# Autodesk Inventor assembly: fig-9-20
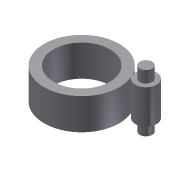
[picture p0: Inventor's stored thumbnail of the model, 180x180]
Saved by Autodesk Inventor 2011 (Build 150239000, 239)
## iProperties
Shininess: 64.0
Length Units: 11269
Angle Units: 11279
Time Units: 11290
Mass Units: 11283
Length Display Precision: 3
Angle Display Precision: 2
Created: 2002-01
Part Number: fig-9-20
Document SubType Name: Assembly
Designer: ***
Density: 0.0
Volumn: 0.0
Area: 0.0
PropertySet Name: Model Information
Control State: 0
Master: False
Checked Out: False
Author: ***
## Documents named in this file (3)
- C:\Users\CADSoft\Desktop\part files\c09-inv-2011-prt\fig-9-20.iam
- C:\Users\CADSoft\Desktop\inventor\c09-inv-2010-prt\c09\Part8.ipt
- C:\Users\CADSoft\Desktop\inventor\c09-inv-2010-prt\c09\Part9.ipt
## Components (2 placed, 2 different names)
1. Part8:1 — Flush:1
2. Part9:1 — Flush:1
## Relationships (1: Flush 1)
- Flush:1: Part8:1 ↔ Part9:1
